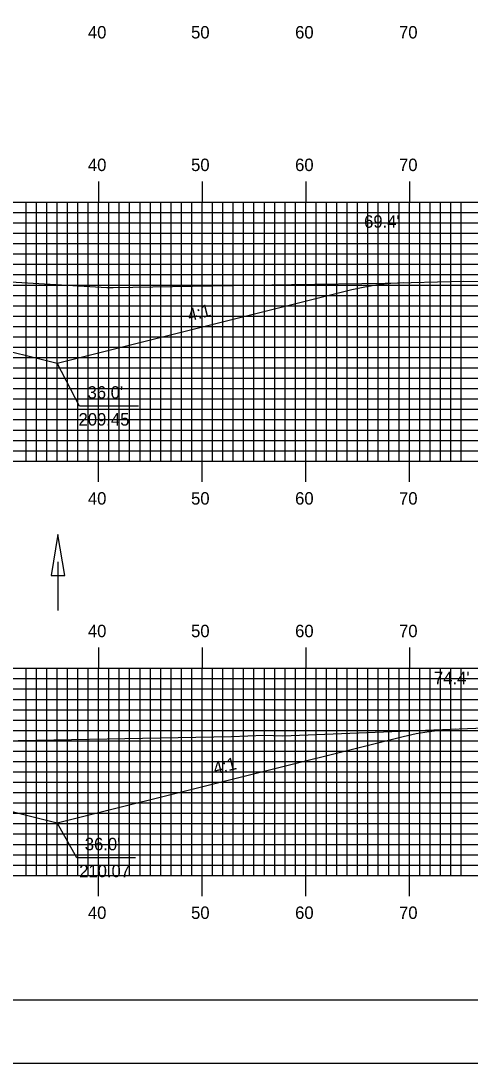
# Model space of a CAD drawing. Extents: x 1821211 to 1821555, y 442591 to 442811.
# Drawn here: x 1821409.7 to 1821453.1, y 442590.5 to 442691.2 of the extents above; entities that cross this region are included whole.
import ezdxf

# ---------------------------------------------------------------- set-up
doc = ezdxf.new("R2010")
doc.units = 0
for name, color, linetype in [('ANNOTATION', 7, 'Continuous'), ('BORDER', 7, 'Continuous'), ('D_Drainage_Ditch_Line', 7, 'Continuous'), ('D_Roadway_Centerline', 7, 'Continuous'), ('D_Roadway_SlopeLines', 7, 'Continuous'), ('D_Text_Standard', 7, 'Continuous'), ('H_V ANNOTATION', 7, 'Continuous'), ('MAJOR', 7, 'Continuous'), ('MINOR', 7, 'Continuous'), ('PLOT BOUNDARY', 7, 'Continuous'), ('S_Roadway_Centerline', 7, 'Continuous')]:
    doc.layers.add(name, color=color, linetype=linetype)

msp = doc.modelspace()

# ---------------------------------------------------------------- linework, layer by layer
at = {"layer": 'ANNOTATION'}
for points in [[(1821421.08, 442653.97), (1821415.39, 442653.97), (1821413.23, 442658.11)], [(1821420.81, 442610.37), (1821415.12, 442610.37), (1821413.23, 442613.74)]]:
    msp.add_lwpolyline(points, dxfattribs=at)
at = {"layer": 'BORDER'}
msp.add_lwpolyline([(1821227.63, 442596.67), (1821547.63, 442596.67), (1821547.63, 442806.67), (1821227.63, 442806.67)], close=True, dxfattribs=at)
at = {"layer": 'D_Drainage_Ditch_Line'}
msp.add_line((1821413.31, 442638.94), (1821413.31, 442634.25), dxfattribs=at)
msp.add_lwpolyline([(1821412.66, 442637.63), (1821413.97, 442637.63), (1821413.31, 442641.57)], close=True, dxfattribs=at)
at = {"layer": 'D_Roadway_Centerline'}
msp.add_lwpolyline([(1821315.24, 442620.07), (1821316.49, 442620.04), (1821317.74, 442619.94), (1821318.99, 442619.75), (1821320.24, 442619.48), (1821343.06, 442613.77), (1821347.06, 442614.77), (1821357.23, 442617.32), (1821365.23, 442617.64), (1821377.23, 442617.88), (1821389.23, 442617.64), (1821399.23, 442617.24), (1821409.23, 442614.74), (1821413.23, 442613.74), (1821446.64, 442622.09), (1821447.89, 442622.37), (1821449.14, 442622.58), (1821450.39, 442622.73), (1821451.64, 442622.81)], dxfattribs=at)
at = {"layer": 'D_Roadway_SlopeLines'}
for points in [[(1821413.23, 442658.11), (1821441.68, 442665.22), (1821442.93, 442665.5), (1821444.18, 442665.71), (1821445.43, 442665.84), (1821446.68, 442665.9)], [(1821399.23, 442661.61), (1821413.23, 442658.11)], [(1821413.23, 442613.74), (1821446.64, 442622.09), (1821447.89, 442622.37), (1821449.14, 442622.58), (1821450.39, 442622.73), (1821451.64, 442622.81)], [(1821399.23, 442617.24), (1821413.23, 442613.74)]]:
    msp.add_lwpolyline(points, dxfattribs=at)
at = {"layer": 'MAJOR'}
for p, q in [((1821417.23, 442675.67), (1821417.23, 442673.67)), ((1821427.23, 442675.67), (1821427.23, 442673.67)), ((1821437.23, 442675.67), (1821437.23, 442673.67)), ((1821447.23, 442675.67), (1821447.23, 442673.67)), ((1821237.23, 442673.67), (1821517.23, 442673.67)), ((1821237.23, 442673.67), (1821517.23, 442673.67)), ((1821417.23, 442648.67), (1821417.23, 442673.67)), ((1821427.23, 442648.67), (1821427.23, 442673.67)), ((1821437.23, 442648.67), (1821437.23, 442673.67)), ((1821447.23, 442648.67), (1821447.23, 442673.67)), ((1821237.23, 442668.67), (1821517.23, 442668.67)), ((1821237.23, 442663.67), (1821517.23, 442663.67)), ((1821237.23, 442658.67), (1821517.23, 442658.67)), ((1821237.23, 442653.67), (1821517.23, 442653.67)), ((1821237.23, 442648.67), (1821517.23, 442648.67)), ((1821237.23, 442648.67), (1821517.23, 442648.67)), ((1821417.23, 442646.66), (1821417.23, 442648.67)), ((1821427.23, 442646.66), (1821427.23, 442648.67)), ((1821437.23, 442646.66), (1821437.23, 442648.67)), ((1821447.23, 442646.66), (1821447.23, 442648.67)), ((1821417.23, 442630.67), (1821417.23, 442628.67)), ((1821427.23, 442630.67), (1821427.23, 442628.67)), ((1821437.23, 442630.67), (1821437.23, 442628.67)), ((1821447.23, 442630.67), (1821447.23, 442628.67)), ((1821237.23, 442628.67), (1821517.23, 442628.67)), ((1821237.23, 442628.67), (1821517.23, 442628.67)), ((1821417.23, 442608.67), (1821417.23, 442628.67)), ((1821427.23, 442608.67), (1821427.23, 442628.67)), ((1821437.23, 442608.67), (1821437.23, 442628.67)), ((1821447.23, 442608.67), (1821447.23, 442628.67)), ((1821237.23, 442623.67), (1821517.23, 442623.67)), ((1821237.23, 442618.67), (1821517.23, 442618.67)), ((1821237.23, 442613.67), (1821517.23, 442613.67)), ((1821237.23, 442608.67), (1821517.23, 442608.67)), ((1821237.23, 442608.67), (1821517.23, 442608.67)), ((1821417.23, 442606.66), (1821417.23, 442608.67)), ((1821427.23, 442606.66), (1821427.23, 442608.67)), ((1821437.23, 442606.66), (1821437.23, 442608.67)), ((1821447.23, 442606.66), (1821447.23, 442608.67))]:
    msp.add_line(p, q, dxfattribs=at)
at = {"layer": 'MINOR'}
for p, q in [((1821410.23, 442648.67), (1821410.23, 442673.67)), ((1821411.23, 442648.67), (1821411.23, 442673.67)), ((1821412.23, 442648.67), (1821412.23, 442673.67)), ((1821413.23, 442648.67), (1821413.23, 442673.67)), ((1821414.23, 442648.67), (1821414.23, 442673.67)), ((1821415.23, 442648.67), (1821415.23, 442673.67)), ((1821416.23, 442648.67), (1821416.23, 442673.67)), ((1821418.23, 442648.67), (1821418.23, 442673.67)), ((1821419.23, 442648.67), (1821419.23, 442673.67)), ((1821420.23, 442648.67), (1821420.23, 442673.67)), ((1821421.23, 442648.67), (1821421.23, 442673.67)), ((1821422.23, 442648.67), (1821422.23, 442673.67)), ((1821423.23, 442648.67), (1821423.23, 442673.67)), ((1821424.23, 442648.67), (1821424.23, 442673.67)), ((1821425.23, 442648.67), (1821425.23, 442673.67)), ((1821426.23, 442648.67), (1821426.23, 442673.67)), ((1821428.23, 442648.67), (1821428.23, 442673.67)), ((1821429.23, 442648.67), (1821429.23, 442673.67)), ((1821430.23, 442648.67), (1821430.23, 442673.67)), ((1821431.23, 442648.67), (1821431.23, 442673.67)), ((1821432.23, 442648.67), (1821432.23, 442673.67)), ((1821433.23, 442648.67), (1821433.23, 442673.67)), ((1821434.23, 442648.67), (1821434.23, 442673.67)), ((1821435.23, 442648.67), (1821435.23, 442673.67)), ((1821436.23, 442648.67), (1821436.23, 442673.67)), ((1821438.23, 442648.67), (1821438.23, 442673.67)), ((1821439.23, 442648.67), (1821439.23, 442673.67)), ((1821440.23, 442648.67), (1821440.23, 442673.67)), ((1821441.23, 442648.67), (1821441.23, 442673.67)), ((1821442.23, 442648.67), (1821442.23, 442673.67)), ((1821443.23, 442648.67), (1821443.23, 442673.67)), ((1821444.23, 442648.67), (1821444.23, 442673.67)), ((1821445.23, 442648.67), (1821445.23, 442673.67)), ((1821446.23, 442648.67), (1821446.23, 442673.67)), ((1821448.23, 442648.67), (1821448.23, 442673.67)), ((1821449.23, 442648.67), (1821449.23, 442673.67)), ((1821450.23, 442648.67), (1821450.23, 442673.67)), ((1821451.23, 442648.67), (1821451.23, 442673.67)), ((1821452.23, 442648.67), (1821452.23, 442673.67)), ((1821237.23, 442672.67), (1821517.23, 442672.67)), ((1821237.23, 442671.67), (1821517.23, 442671.67)), ((1821237.23, 442670.67), (1821517.23, 442670.67)), ((1821237.23, 442669.67), (1821517.23, 442669.67)), ((1821237.23, 442667.67), (1821517.23, 442667.67)), ((1821237.23, 442666.67), (1821517.23, 442666.67)), ((1821237.23, 442665.67), (1821517.23, 442665.67)), ((1821237.23, 442664.67), (1821517.23, 442664.67)), ((1821237.23, 442662.67), (1821517.23, 442662.67)), ((1821237.23, 442661.67), (1821517.23, 442661.67)), ((1821237.23, 442660.67), (1821517.23, 442660.67)), ((1821237.23, 442659.67), (1821517.23, 442659.67)), ((1821237.23, 442657.67), (1821517.23, 442657.67)), ((1821237.23, 442656.67), (1821517.23, 442656.67)), ((1821237.23, 442655.67), (1821517.23, 442655.67)), ((1821237.23, 442654.67), (1821517.23, 442654.67)), ((1821237.23, 442652.67), (1821517.23, 442652.67)), ((1821237.23, 442651.67), (1821517.23, 442651.67)), ((1821237.23, 442650.67), (1821517.23, 442650.67)), ((1821237.23, 442649.67), (1821517.23, 442649.67)), ((1821410.23, 442608.67), (1821410.23, 442628.67)), ((1821411.23, 442608.67), (1821411.23, 442628.67)), ((1821412.23, 442608.67), (1821412.23, 442628.67)), ((1821413.23, 442608.67), (1821413.23, 442628.67)), ((1821414.23, 442608.67), (1821414.23, 442628.67)), ((1821415.23, 442608.67), (1821415.23, 442628.67)), ((1821416.23, 442608.67), (1821416.23, 442628.67)), ((1821418.23, 442608.67), (1821418.23, 442628.67)), ((1821419.23, 442608.67), (1821419.23, 442628.67)), ((1821420.23, 442608.67), (1821420.23, 442628.67)), ((1821421.23, 442608.67), (1821421.23, 442628.67)), ((1821422.23, 442608.67), (1821422.23, 442628.67)), ((1821423.23, 442608.67), (1821423.23, 442628.67)), ((1821424.23, 442608.67), (1821424.23, 442628.67)), ((1821425.23, 442608.67), (1821425.23, 442628.67)), ((1821426.23, 442608.67), (1821426.23, 442628.67)), ((1821428.23, 442608.67), (1821428.23, 442628.67)), ((1821429.23, 442608.67), (1821429.23, 442628.67)), ((1821430.23, 442608.67), (1821430.23, 442628.67)), ((1821431.23, 442608.67), (1821431.23, 442628.67)), ((1821432.23, 442608.67), (1821432.23, 442628.67)), ((1821433.23, 442608.67), (1821433.23, 442628.67)), ((1821434.23, 442608.67), (1821434.23, 442628.67)), ((1821435.23, 442608.67), (1821435.23, 442628.67)), ((1821436.23, 442608.67), (1821436.23, 442628.67)), ((1821438.23, 442608.67), (1821438.23, 442628.67)), ((1821439.23, 442608.67), (1821439.23, 442628.67)), ((1821440.23, 442608.67), (1821440.23, 442628.67)), ((1821441.23, 442608.67), (1821441.23, 442628.67)), ((1821442.23, 442608.67), (1821442.23, 442628.67)), ((1821443.23, 442608.67), (1821443.23, 442628.67)), ((1821444.23, 442608.67), (1821444.23, 442628.67)), ((1821445.23, 442608.67), (1821445.23, 442628.67)), ((1821446.23, 442608.67), (1821446.23, 442628.67)), ((1821448.23, 442608.67), (1821448.23, 442628.67)), ((1821449.23, 442608.67), (1821449.23, 442628.67)), ((1821450.23, 442608.67), (1821450.23, 442628.67)), ((1821451.23, 442608.67), (1821451.23, 442628.67)), ((1821452.23, 442608.67), (1821452.23, 442628.67)), ((1821237.23, 442627.67), (1821517.23, 442627.67)), ((1821237.23, 442626.67), (1821517.23, 442626.67)), ((1821237.23, 442625.67), (1821517.23, 442625.67)), ((1821237.23, 442624.67), (1821517.23, 442624.67)), ((1821237.23, 442622.67), (1821517.23, 442622.67)), ((1821237.23, 442621.67), (1821517.23, 442621.67)), ((1821237.23, 442620.67), (1821517.23, 442620.67)), ((1821237.23, 442619.67), (1821517.23, 442619.67)), ((1821237.23, 442617.67), (1821517.23, 442617.67)), ((1821237.23, 442616.67), (1821517.23, 442616.67)), ((1821237.23, 442615.67), (1821517.23, 442615.67)), ((1821237.23, 442614.67), (1821517.23, 442614.67)), ((1821237.23, 442612.67), (1821517.23, 442612.67)), ((1821237.23, 442611.67), (1821517.23, 442611.67)), ((1821237.23, 442610.67), (1821517.23, 442610.67)), ((1821237.23, 442609.67), (1821517.23, 442609.67))]:
    msp.add_line(p, q, dxfattribs=at)
at = {"layer": 'PLOT BOUNDARY'}
msp.add_lwpolyline([(1821211.44, 442590.55), (1821551.44, 442590.55), (1821551.44, 442810.55), (1821211.44, 442810.55)], close=True, dxfattribs=at)
at = {"layer": 'S_Roadway_Centerline'}
for points in [[(1821319.61, 442662.84), (1821333.56, 442663.19), (1821350.85, 442663.66), (1821351.69, 442663.68), (1821353.67, 442663.78), (1821385.88, 442665.14), (1821395.98, 442665.86), (1821406.52, 442666.12), (1821418.04, 442665.43), (1821418.63, 442665.43), (1821435.85, 442665.72), (1821444.88, 442665.86), (1821452.44, 442666.04), (1821463.84, 442666.01), (1821469.26, 442666.15), (1821479.16, 442666.31), (1821486.68, 442666.44), (1821500.06, 442666.4), (1821503.32, 442666.34), (1821509.48, 442666.37), (1821517.23, 442666.37)], [(1821320.8, 442620.15), (1821334.26, 442620.5), (1821362.26, 442621.17), (1821365.11, 442621.23), (1821366.24, 442621.25), (1821389.98, 442621.42), (1821402.6, 442621.57), (1821430.07, 442622.08), (1821433.21, 442622.22), (1821435, 442622.15), (1821456.9, 442623.02), (1821466.5, 442622.85), (1821473, 442623.01), (1821482.64, 442622.69), (1821490.54, 442622.39), (1821507.18, 442622.78), (1821517.07, 442622.84), (1821517.23, 442622.83)]]:
    msp.add_lwpolyline(points, dxfattribs=at)

# ---------------------------------------------------------------- texts
at = {"layer": 'ANNOTATION'}
for p in [(1821425.99, 442662.16), (1821428.47, 442618.41)]:
    msp.add_text('4:1', height=1.2, rotation=14.0362, dxfattribs=at).set_placement(p)
for s, p in [("36.0'", (1821416.17, 442654.7)), ('209.45', (1821415.3, 442652.1)), ("36.0'", (1821415.9, 442611.1)), ('210.07', (1821415.36, 442608.5))]:
    msp.add_text(s, height=1.2, dxfattribs=at).set_placement(p)
at = {"layer": 'D_Text_Standard'}
for s, p in [("69.4'", (1821442.86, 442671.2)), ("74.4'", (1821449.6, 442627.13))]:
    msp.add_text(s, height=1.2, dxfattribs=at).set_placement(p)
at = {"layer": 'H_V ANNOTATION'}
for s, p in [('40', (1821416.2, 442689.47)), ('50', (1821426.16, 442689.47)), ('60', (1821436.2, 442689.47)), ('70', (1821446.23, 442689.47)), ('40', (1821416.2, 442676.67)), ('50', (1821426.16, 442676.67)), ('60', (1821436.2, 442676.67)), ('70', (1821446.23, 442676.67)), ('40', (1821416.2, 442644.47)), ('50', (1821426.16, 442644.47)), ('60', (1821436.2, 442644.47)), ('70', (1821446.23, 442644.47)), ('40', (1821416.2, 442631.67)), ('50', (1821426.16, 442631.67)), ('60', (1821436.2, 442631.67)), ('70', (1821446.23, 442631.67)), ('40', (1821416.2, 442604.47)), ('50', (1821426.16, 442604.47)), ('60', (1821436.2, 442604.47)), ('70', (1821446.23, 442604.47))]:
    msp.add_text(s, height=1.2, dxfattribs=at).set_placement(p)

doc.saveas('drawing.dxf')
